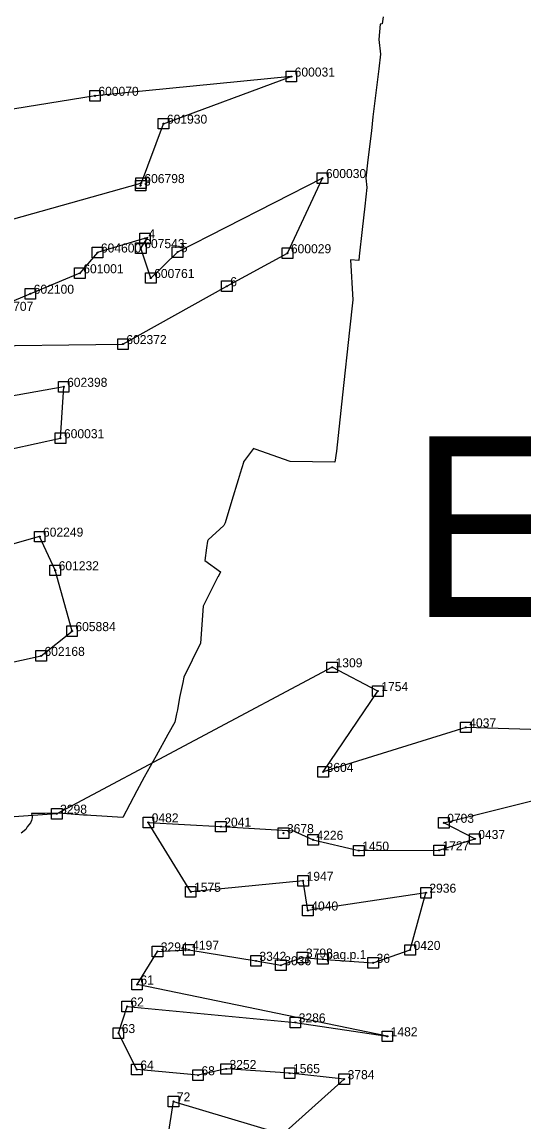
# Model space of a CAD drawing. Extents: x 462479 to 502016, y 241775 to 305873.
# Drawn here: x 478531 to 481857, y 250516 to 257820 of the extents above; entities that cross this region are included whole.
import ezdxf

# ---------------------------------------------------------------- set-up
doc = ezdxf.new("R2010")
doc.units = 0
for name, color, linetype in [('Default', 7, 'Continuous'), ('Level 19', 7, 'Continuous'), ('Level 51', 7, 'Continuous'), ('pagastu_nosaukumi', 7, 'Continuous'), ('pagastu_robezas', 7, 'Continuous')]:
    doc.layers.add(name, color=color, linetype=linetype)

msp = doc.modelspace()

# ---------------------------------------------------------------- linework, layer by layer
at = {"layer": 'Default'}
for points in [[(477812.9, 256327.6), (479320.6, 256750.3), (479318.1, 256733.4), (479470.4, 257144.7), (480318.7, 257457.6), (479015.3, 257329.8), (477784.6, 257129.8)], [(478123.9, 255667.8), (479201, 255681.3), (479891, 256065.7), (480293.6, 256284.5), (480525.8, 256783.7), (479562.7, 256291.9), (479385.7, 256120.1), (479319.9, 256318.4), (479366.3, 256388.8), (479032.1, 256289.4), (478915.1, 256151.7), (478585.9, 256015.6), (478315.6, 255902.1)], [(477814.9, 254844.2), (478786.8, 255056.3), (478807.5, 255397.6), (477838.5, 255223.9)], [(478003.4, 253467.4), (478657.4, 253610.8), (478862.7, 253775.4), (478751.3, 254179.4), (478647.6, 254402.7), (477546.7, 254091.6)], [(483413.2, 253074.8), (481478.2, 253136.4), (480530.5, 252840.5), (480894, 253377.2), (480590.4, 253535.2), (478761.2, 252562.9), (477780.4, 252492.7)], [(479499.4, 250412), (479536.6, 250652.6), (480263.2, 250435.7), (480670.4, 250800.4), (480308, 250840.1), (479886.1, 250868), (479699.6, 250826.5), (479293.6, 250864.3), (479170.4, 251106.6), (479228, 251283.1), (480345.5, 251177.2), (480956.2, 251085.1), (479294.5, 251428.9), (479429.7, 251648.6), (479637.8, 251659.4), (480084.6, 251586.1), (480249.8, 251556.8), (480393.6, 251607.8), (480579.8, 251593.8), (480862.8, 251573), (481108.4, 251658.5), (481213, 252038.4), (480429, 251920.3), (480397.8, 252117.5), (479650.8, 252044.3), (479369.2, 252505.4), (479851.3, 252477.2), (480333.5, 252449.1), (480463.4, 252389.8), (480767.1, 252317.8), (481299.9, 252320.1), (481537.6, 252395.2), (481331.4, 252502.6), (482023.1, 252674.5)]]:
    msp.add_lwpolyline(points, dxfattribs=at)
at = {"layer": 'Level 19'}
for p, q in [((480283.7, 257492.6), (480353.7, 257492.6)), ((480283.7, 257422.6), (480283.7, 257492.6)), ((480353.7, 257492.6), (480353.7, 257422.6)), ((480353.7, 257422.6), (480283.7, 257422.6)), ((478980.3, 257364.8), (479050.3, 257364.8)), ((478980.3, 257294.8), (478980.3, 257364.8)), ((479050.3, 257364.8), (479050.3, 257294.8)), ((479050.3, 257294.8), (478980.3, 257294.8)), ((479435.4, 257179.7), (479505.4, 257179.7)), ((479435.4, 257109.7), (479435.4, 257179.7)), ((479505.4, 257179.7), (479505.4, 257109.7)), ((479505.4, 257109.7), (479435.4, 257109.7)), ((480490.8, 256818.7), (480560.8, 256818.7)), ((480490.8, 256748.7), (480490.8, 256818.7)), ((480560.8, 256818.7), (480560.8, 256748.7)), ((479283.1, 256768.4), (479353.1, 256768.4)), ((479283.1, 256698.4), (479283.1, 256768.4)), ((479285.6, 256785.3), (479355.6, 256785.3)), ((479285.6, 256715.3), (479285.6, 256785.3)), ((479353.1, 256768.4), (479353.1, 256698.4)), ((479355.6, 256785.3), (479355.6, 256715.3)), ((480560.8, 256748.7), (480490.8, 256748.7)), ((479353.1, 256698.4), (479283.1, 256698.4)), ((479355.6, 256715.3), (479285.6, 256715.3)), ((479312.4, 256417.8), (479382.4, 256417.8)), ((479312.4, 256347.8), (479312.4, 256417.8)), ((479382.4, 256417.8), (479382.4, 256347.8)), ((478997.1, 256324.4), (479067.1, 256324.4)), ((478997.1, 256254.4), (478997.1, 256324.4)), ((479067.1, 256324.4), (479067.1, 256254.4)), ((479284.9, 256353.4), (479354.9, 256353.4)), ((479284.9, 256283.4), (479284.9, 256353.4)), ((479284.9, 256353.4), (479354.9, 256353.4)), ((479284.9, 256283.4), (479284.9, 256353.4)), ((479382.4, 256347.8), (479312.4, 256347.8)), ((479354.9, 256353.4), (479354.9, 256283.4)), ((479354.9, 256353.4), (479354.9, 256283.4)), ((479527.7, 256326.9), (479597.7, 256326.9)), ((479527.7, 256256.9), (479527.7, 256326.9)), ((479597.7, 256326.9), (479597.7, 256256.9)), ((480258.6, 256319.5), (480328.6, 256319.5)), ((480258.6, 256249.5), (480258.6, 256319.5)), ((480328.6, 256319.5), (480328.6, 256249.5)), ((479067.1, 256254.4), (478997.1, 256254.4)), ((479354.9, 256283.4), (479284.9, 256283.4)), ((479354.9, 256283.4), (479284.9, 256283.4)), ((479597.7, 256256.9), (479527.7, 256256.9)), ((480328.6, 256249.5), (480258.6, 256249.5)), ((478880.1, 256186.7), (478950.1, 256186.7)), ((478880.1, 256116.7), (478880.1, 256186.7)), ((478950.1, 256186.7), (478950.1, 256116.7)), ((479350.7, 256155.1), (479420.7, 256155.1)), ((479350.7, 256085.1), (479350.7, 256155.1)), ((479420.7, 256155.1), (479420.7, 256085.1)), ((478950.1, 256116.7), (478880.1, 256116.7)), ((479420.7, 256085.1), (479350.7, 256085.1)), ((479856, 256100.7), (479926, 256100.7)), ((479856, 256030.7), (479856, 256100.7)), ((479926, 256100.7), (479926, 256030.7)), ((478550.9, 256050.6), (478620.9, 256050.6)), ((478550.9, 255980.6), (478550.9, 256050.6)), ((478620.9, 256050.6), (478620.9, 255980.6)), ((479926, 256030.7), (479856, 256030.7)), ((478620.9, 255980.6), (478550.9, 255980.6)), ((479166, 255716.3), (479236, 255716.3)), ((479166, 255646.3), (479166, 255716.3)), ((479236, 255716.3), (479236, 255646.3)), ((479236, 255646.3), (479166, 255646.3)), ((478772.5, 255432.6), (478842.5, 255432.6)), ((478772.5, 255362.6), (478772.5, 255432.6)), ((478842.5, 255432.6), (478842.5, 255362.6)), ((478842.5, 255362.6), (478772.5, 255362.6)), ((478751.8, 255091.3), (478821.8, 255091.3)), ((478751.8, 255021.3), (478751.8, 255091.3)), ((478821.8, 255091.3), (478821.8, 255021.3)), ((478821.8, 255021.3), (478751.8, 255021.3)), ((478612.6, 254437.7), (478682.6, 254437.7)), ((478612.6, 254367.7), (478612.6, 254437.7)), ((478682.6, 254437.7), (478682.6, 254367.7)), ((478682.6, 254367.7), (478612.6, 254367.7)), ((478716.3, 254214.4), (478786.3, 254214.4)), ((478716.3, 254144.4), (478716.3, 254214.4)), ((478786.3, 254214.4), (478786.3, 254144.4)), ((478786.3, 254144.4), (478716.3, 254144.4)), ((478827.7, 253810.4), (478897.7, 253810.4)), ((478827.7, 253740.4), (478827.7, 253810.4)), ((478897.7, 253740.4), (478827.7, 253740.4)), ((478897.7, 253810.4), (478897.7, 253740.4)), ((478622.4, 253645.8), (478692.4, 253645.8)), ((478622.4, 253575.8), (478622.4, 253645.8)), ((478692.4, 253645.8), (478692.4, 253575.8)), ((478692.4, 253575.8), (478622.4, 253575.8)), ((480555.4, 253570.2), (480625.4, 253570.2)), ((480555.4, 253500.2), (480555.4, 253570.2)), ((480625.4, 253570.2), (480625.4, 253500.2)), ((480625.4, 253500.2), (480555.4, 253500.2)), ((480859, 253412.2), (480929, 253412.2)), ((480859, 253342.2), (480859, 253412.2)), ((480929, 253412.2), (480929, 253342.2)), ((480929, 253342.2), (480859, 253342.2)), ((481443.2, 253171.4), (481513.2, 253171.4)), ((481443.2, 253101.4), (481443.2, 253171.4)), ((481513.2, 253171.4), (481513.2, 253101.4)), ((481513.2, 253101.4), (481443.2, 253101.4)), ((480495.5, 252875.5), (480565.5, 252875.5)), ((480495.5, 252805.5), (480495.5, 252875.5)), ((480565.5, 252875.5), (480565.5, 252805.5)), ((480565.5, 252805.5), (480495.5, 252805.5)), ((478726.2, 252597.9), (478796.2, 252597.9)), ((478726.2, 252527.9), (478726.2, 252597.9)), ((478796.2, 252597.9), (478796.2, 252527.9)), ((478796.2, 252527.9), (478726.2, 252527.9)), ((479334.2, 252540.4), (479404.2, 252540.4)), ((479334.2, 252470.4), (479334.2, 252540.4)), ((479334.2, 252540.4), (479404.2, 252540.4)), ((479334.2, 252470.4), (479334.2, 252540.4)), ((479334.2, 252540.4), (479404.2, 252540.4)), ((479334.2, 252470.4), (479334.2, 252540.4)), ((479404.2, 252540.4), (479404.2, 252470.4)), ((479404.2, 252540.4), (479404.2, 252470.4)), ((479404.2, 252540.4), (479404.2, 252470.4)), ((479816.3, 252512.2), (479886.3, 252512.2)), ((479816.3, 252442.2), (479816.3, 252512.2)), ((479886.3, 252512.2), (479886.3, 252442.2)), ((481296.4, 252537.6), (481366.4, 252537.6)), ((481296.4, 252467.6), (481296.4, 252537.6)), ((481366.4, 252537.6), (481366.4, 252467.6)), ((479404.2, 252470.4), (479334.2, 252470.4)), ((479404.2, 252470.4), (479334.2, 252470.4)), ((479404.2, 252470.4), (479334.2, 252470.4)), ((479886.3, 252442.2), (479816.3, 252442.2)), ((480232.5, 252469), (480302.5, 252469)), ((480232.5, 252399), (480232.5, 252469)), ((480302.5, 252469), (480302.5, 252399)), ((480428.4, 252424.8), (480498.4, 252424.8)), ((480428.4, 252354.8), (480428.4, 252424.8)), ((480498.4, 252424.8), (480498.4, 252354.8)), ((481366.4, 252467.6), (481296.4, 252467.6)), ((481502.6, 252430.2), (481572.6, 252430.2)), ((481502.6, 252360.2), (481502.6, 252430.2)), ((481572.6, 252430.2), (481572.6, 252360.2)), ((480302.5, 252399), (480232.5, 252399)), ((480498.4, 252354.8), (480428.4, 252354.8)), ((480732.1, 252352.8), (480802.1, 252352.8)), ((480732.1, 252282.8), (480732.1, 252352.8)), ((480802.1, 252352.8), (480802.1, 252282.8)), ((481264.9, 252355.1), (481334.9, 252355.1)), ((481264.9, 252285.1), (481264.9, 252355.1)), ((481264.9, 252355.1), (481334.9, 252355.1)), ((481264.9, 252285.1), (481264.9, 252355.1)), ((481264.9, 252355.1), (481334.9, 252355.1)), ((481264.9, 252285.1), (481264.9, 252355.1)), ((481264.9, 252355.1), (481334.9, 252355.1)), ((481264.9, 252285.1), (481264.9, 252355.1)), ((481334.9, 252355.1), (481334.9, 252285.1)), ((481334.9, 252355.1), (481334.9, 252285.1)), ((481334.9, 252355.1), (481334.9, 252285.1)), ((481334.9, 252355.1), (481334.9, 252285.1)), ((481572.6, 252360.2), (481502.6, 252360.2)), ((480802.1, 252282.8), (480732.1, 252282.8)), ((481334.9, 252285.1), (481264.9, 252285.1)), ((481334.9, 252285.1), (481264.9, 252285.1)), ((481334.9, 252285.1), (481264.9, 252285.1)), ((481334.9, 252285.1), (481264.9, 252285.1)), ((480362.8, 252152.5), (480432.8, 252152.5)), ((480362.8, 252082.5), (480362.8, 252152.5)), ((480362.8, 252152.5), (480432.8, 252152.5)), ((480362.8, 252082.5), (480362.8, 252152.5)), ((480362.8, 252152.5), (480432.8, 252152.5)), ((480362.8, 252082.5), (480362.8, 252152.5)), ((480362.8, 252152.5), (480432.8, 252152.5)), ((480362.8, 252082.5), (480362.8, 252152.5)), ((480432.8, 252152.5), (480432.8, 252082.5)), ((480432.8, 252152.5), (480432.8, 252082.5)), ((480432.8, 252152.5), (480432.8, 252082.5)), ((480432.8, 252152.5), (480432.8, 252082.5)), ((479615.8, 252079.3), (479685.8, 252079.3)), ((479615.8, 252009.3), (479615.8, 252079.3)), ((479685.8, 252079.3), (479685.8, 252009.3)), ((480432.8, 252082.5), (480362.8, 252082.5)), ((480432.8, 252082.5), (480362.8, 252082.5)), ((480432.8, 252082.5), (480362.8, 252082.5)), ((480432.8, 252082.5), (480362.8, 252082.5)), ((481178, 252073.4), (481248, 252073.4)), ((481178, 252003.4), (481178, 252073.4)), ((481248, 252073.4), (481248, 252003.4)), ((479685.8, 252009.3), (479615.8, 252009.3)), ((481248, 252003.4), (481178, 252003.4)), ((480394, 251955.3), (480464, 251955.3)), ((480394, 251885.3), (480394, 251955.3)), ((480464, 251955.3), (480464, 251885.3)), ((480464, 251885.3), (480394, 251885.3)), ((479602.8, 251694.4), (479672.8, 251694.4)), ((479602.8, 251624.4), (479602.8, 251694.4)), ((479672.8, 251694.4), (479672.8, 251624.4)), ((479394.7, 251683.6), (479464.7, 251683.6)), ((479394.7, 251613.6), (479394.7, 251683.6)), ((479464.7, 251683.6), (479464.7, 251613.6)), ((479672.8, 251624.4), (479602.8, 251624.4)), ((480049.6, 251621.1), (480119.6, 251621.1)), ((480049.6, 251551.1), (480049.6, 251621.1)), ((480119.6, 251621.1), (480119.6, 251551.1)), ((480358.6, 251642.8), (480428.6, 251642.8)), ((480358.6, 251572.8), (480358.6, 251642.8)), ((480358.6, 251642.8), (480428.6, 251642.8)), ((480358.6, 251572.8), (480358.6, 251642.8)), ((480358.6, 251642.8), (480428.6, 251642.8)), ((480358.6, 251572.8), (480358.6, 251642.8)), ((480358.6, 251642.8), (480428.6, 251642.8)), ((480358.6, 251572.8), (480358.6, 251642.8)), ((480428.6, 251642.8), (480428.6, 251572.8)), ((480428.6, 251642.8), (480428.6, 251572.8)), ((480428.6, 251642.8), (480428.6, 251572.8)), ((480428.6, 251642.8), (480428.6, 251572.8)), ((480492.5, 251633.2), (480562.5, 251633.2)), ((480492.5, 251563.2), (480492.5, 251633.2)), ((480562.5, 251633.2), (480562.5, 251563.2)), ((481073.4, 251693.5), (481143.4, 251693.5)), ((481073.4, 251623.5), (481073.4, 251693.5)), ((481073.4, 251693.5), (481143.4, 251693.5)), ((481073.4, 251623.5), (481073.4, 251693.5)), ((481073.4, 251693.5), (481143.4, 251693.5)), ((481073.4, 251623.5), (481073.4, 251693.5)), ((481143.4, 251623.5), (481073.4, 251623.5)), ((481143.4, 251623.5), (481073.4, 251623.5)), ((481143.4, 251623.5), (481073.4, 251623.5)), ((481143.4, 251693.5), (481143.4, 251623.5)), ((481143.4, 251693.5), (481143.4, 251623.5)), ((481143.4, 251693.5), (481143.4, 251623.5)), ((479464.7, 251613.6), (479394.7, 251613.6)), ((480119.6, 251551.1), (480049.6, 251551.1)), ((480214.8, 251591.8), (480284.8, 251591.8)), ((480214.8, 251521.8), (480214.8, 251591.8)), ((480284.8, 251591.8), (480284.8, 251521.8)), ((480428.6, 251572.8), (480358.6, 251572.8)), ((480428.6, 251572.8), (480358.6, 251572.8)), ((480428.6, 251572.8), (480358.6, 251572.8)), ((480428.6, 251572.8), (480358.6, 251572.8)), ((480562.5, 251563.2), (480492.5, 251563.2)), ((480827.8, 251608), (480897.8, 251608)), ((480827.8, 251538), (480827.8, 251608)), ((480897.8, 251608), (480897.8, 251538)), ((480284.8, 251521.8), (480214.8, 251521.8)), ((480897.8, 251538), (480827.8, 251538)), ((479259.5, 251463.9), (479329.5, 251463.9)), ((479259.5, 251393.9), (479259.5, 251463.9)), ((479259.5, 251463.9), (479329.5, 251463.9)), ((479259.5, 251393.9), (479259.5, 251463.9)), ((479259.5, 251463.9), (479329.5, 251463.9)), ((479259.5, 251393.9), (479259.5, 251463.9)), ((479329.5, 251463.9), (479329.5, 251393.9)), ((479329.5, 251463.9), (479329.5, 251393.9)), ((479329.5, 251463.9), (479329.5, 251393.9)), ((479329.5, 251393.9), (479259.5, 251393.9)), ((479329.5, 251393.9), (479259.5, 251393.9)), ((479329.5, 251393.9), (479259.5, 251393.9)), ((479193, 251318.1), (479263, 251318.1)), ((479193, 251248.1), (479193, 251318.1)), ((479263, 251318.1), (479263, 251248.1)), ((479263, 251248.1), (479193, 251248.1)), ((480310.5, 251212.2), (480380.5, 251212.2)), ((480310.5, 251142.2), (480310.5, 251212.2)), ((480380.5, 251212.2), (480380.5, 251142.2)), ((479135.4, 251141.6), (479205.4, 251141.6)), ((479135.4, 251071.6), (479135.4, 251141.6)), ((479205.4, 251141.6), (479205.4, 251071.6)), ((480380.5, 251142.2), (480310.5, 251142.2)), ((480921.2, 251120.1), (480991.2, 251120.1)), ((480921.2, 251050.1), (480921.2, 251120.1)), ((480991.2, 251120.1), (480991.2, 251050.1)), ((479205.4, 251071.6), (479135.4, 251071.6)), ((480991.2, 251050.1), (480921.2, 251050.1)), ((479258.6, 250899.3), (479328.6, 250899.3)), ((479258.6, 250829.3), (479258.6, 250899.3)), ((479328.6, 250899.3), (479328.6, 250829.3)), ((479851.1, 250903), (479921.1, 250903)), ((479851.1, 250833), (479851.1, 250903)), ((479921.1, 250903), (479921.1, 250833)), ((479328.6, 250829.3), (479258.6, 250829.3)), ((479664.6, 250861.5), (479734.6, 250861.5)), ((479664.6, 250791.5), (479664.6, 250861.5)), ((479734.6, 250861.5), (479734.6, 250791.5)), ((479921.1, 250833), (479851.1, 250833)), ((480273, 250875.1), (480343, 250875.1)), ((480273, 250805.1), (480273, 250875.1)), ((480273, 250875.1), (480343, 250875.1)), ((480273, 250805.1), (480273, 250875.1)), ((480273, 250875.1), (480343, 250875.1)), ((480273, 250805.1), (480273, 250875.1)), ((480273, 250875.1), (480343, 250875.1)), ((480273, 250805.1), (480273, 250875.1)), ((480343, 250875.1), (480343, 250805.1)), ((480343, 250875.1), (480343, 250805.1)), ((480343, 250875.1), (480343, 250805.1)), ((480343, 250875.1), (480343, 250805.1)), ((480635.4, 250835.4), (480705.4, 250835.4)), ((480635.4, 250765.4), (480635.4, 250835.4)), ((480705.4, 250835.4), (480705.4, 250765.4)), ((479734.6, 250791.5), (479664.6, 250791.5)), ((480343, 250805.1), (480273, 250805.1)), ((480343, 250805.1), (480273, 250805.1)), ((480343, 250805.1), (480273, 250805.1)), ((480343, 250805.1), (480273, 250805.1)), ((480705.4, 250765.4), (480635.4, 250765.4)), ((479501.6, 250687.6), (479571.6, 250687.6)), ((479501.6, 250617.6), (479501.6, 250687.6)), ((479501.6, 250687.6), (479571.6, 250687.6)), ((479501.6, 250617.6), (479501.6, 250687.6)), ((479501.6, 250687.6), (479571.6, 250687.6)), ((479501.6, 250617.6), (479501.6, 250687.6)), ((479571.6, 250687.6), (479571.6, 250617.6)), ((479571.6, 250687.6), (479571.6, 250617.6)), ((479571.6, 250687.6), (479571.6, 250617.6)), ((479571.6, 250617.6), (479501.6, 250617.6)), ((479571.6, 250617.6), (479501.6, 250617.6)), ((479571.6, 250617.6), (479501.6, 250617.6))]:
    msp.add_line(p, q, dxfattribs=at)
for centre in [(480318.7, 257457.6), (479015.3, 257329.8), (479470.4, 257144.7), (479318.2, 256733.4), (479320.6, 256750.2), (480525.8, 256783.7), (479347.4, 256382.8), (479319.9, 256318.4), (479319.9, 256318.4), (479032.1, 256289.3), (479562.8, 256291.9), (480293.6, 256284.5), (478915.1, 256151.7), (479385.7, 256120.1), (478585.9, 256015.6), (479891, 256065.6), (479201, 255681.3), (478807.5, 255397.5), (478786.9, 255056.3), (478647.6, 254402.7), (478751.4, 254179.3), (478862.7, 253775.4), (478657.5, 253610.7), (480590.4, 253535.2), (480894, 253377.2), (481478.2, 253136.4), (480530.5, 252840.5), (478761.2, 252562.9), (479369.2, 252505.3), (479369.2, 252505.3), (479369.2, 252505.3), (481331.4, 252502.6), (479851.4, 252477.2), (480267.6, 252433.9), (480463.4, 252389.8), (481537.6, 252395.2), (480767.2, 252317.8), (481299.9, 252320.1), (481299.9, 252320.1), (481299.9, 252320.1), (481299.9, 252320.1), (480397.8, 252117.5), (480397.8, 252117.5), (480397.8, 252117.5), (480397.8, 252117.5), (479650.9, 252044.3), (481213, 252038.4), (480429.1, 251920.3), (479429.8, 251648.6), (479637.8, 251659.3), (481108.5, 251658.5), (481108.5, 251658.5), (481108.5, 251658.5), (480084.7, 251586), (480249.8, 251556.7), (480393.6, 251607.7), (480393.6, 251607.7), (480393.6, 251607.7), (480393.6, 251607.7), (480527.5, 251598.1), (480862.9, 251573), (479294.5, 251428.9), (479294.5, 251428.9), (479294.5, 251428.9), (479228.1, 251283.1), (479170.5, 251106.6), (480345.5, 251177.1), (480956.2, 251085), (479293.6, 250864.2), (479699.7, 250826.5), (479886.1, 250868), (480308, 250840.1), (480308, 250840.1), (480308, 250840.1), (480308, 250840.1), (480670.4, 250800.4), (479536.7, 250652.6), (479536.7, 250652.6), (479536.7, 250652.6)]:
    msp.add_circle(centre, 3.5, dxfattribs=at)
at = {"layer": 'pagastu_robezas'}
msp.add_lwpolyline([(480928.5, 257855.4), (480921.1, 257807.7), (480909.4, 257806.7), (480901, 257704), (480911.4, 257606.4), (480900.7, 257509.4), (480860.7, 257189.9), (480850.2, 257096.5), (480827.7, 256904.3), (480813.4, 256782.3), (480820.3, 256722.2), (480806, 256597), (480789.4, 256441.8), (480769.9, 256264.5), (480767.5, 256236.7), (480712.9, 256240.7), (480726.7, 255975.4), (480704.2, 255773), (480658.4, 255345.3), (480618.1, 254971.3), (480607.6, 254898.1), (480310.5, 254902.7), (480079.5, 254983.3), (480067.1, 254988.5), (480002, 254898.7), (480000.6, 254895.1), (479979, 254823.4), (479965.7, 254779.2), (479924.4, 254642.3), (479879.4, 254494.2), (479871.3, 254476.5), (479765.9, 254381.7), (479762.1, 254371.7), (479756.2, 254329.2), (479745.3, 254244.7), (479848.8, 254168.9), (479832.4, 254136.7), (479831.6, 254135.2), (479733, 253941.8), (479715.9, 253696), (479605, 253469.3), (479597.5, 253435), (479585, 253373.9), (479577.2, 253333.9), (479563.4, 253253.4), (479557.4, 253226.9), (479544.7, 253171.6), (479499.5, 253090.1), (479421, 252948.3), (479342.3, 252806.2), (479293.9, 252715.1), (479200.1, 252538.3), (479024.4, 252548.9), (478986.9, 252551.2), (478963.2, 252552.6), (478939.1, 252554.3), (478828.4, 252562.2), (478780.5, 252565.6), (478682.6, 252564.1), (478594.3, 252564.3), (478598.9, 252541.5), (478597.3, 252536.3), (478593.9, 252518.9), (478587.5, 252501.5), (478576.5, 252490.3), (478564.8, 252476.4), (478555.6, 252459), (478524, 252433.2)], dxfattribs=at)

# ---------------------------------------------------------------- texts
at = {"layer": 'Level 51'}
for s, p in [(' 600031', (480318.7, 257457.6)), (' 600070', (479015.3, 257329.8)), (' 601930', (479470.4, 257144.7)), (' 606798', (479320.6, 256750.3)), (' 600030', (480525.8, 256783.7)), (' 3', (479318.1, 256733.4)), (' 4', (479347.4, 256382.8)), (' 607543', (479319.9, 256318.4)), (' 607543', (479319.9, 256318.4)), (' 604600', (479032.1, 256289.4)), (' 5', (479562.7, 256291.9)), (' 600029', (480293.6, 256284.5)), (' 601001', (478915.1, 256151.7)), (' 600761', (479385.7, 256120.1)), (' 602100', (478585.9, 256015.6)), (' 6', (479891, 256065.7)), (' 606707', (478315.6, 255902.1)), (' 602372', (479201, 255681.3)), (' 602398', (478807.5, 255397.6)), (' 600031', (478786.8, 255056.3)), (' 602249', (478647.6, 254402.7)), (' 601232', (478751.3, 254179.4)), (' 605884', (478862.7, 253775.4)), (' 602168', (478657.4, 253610.8)), (' 1309', (480590.4, 253535.2)), (' 1754', (480894, 253377.2)), (' 4037', (481478.2, 253136.4)), (' 3604', (480530.5, 252840.5)), (' 3298', (478761.2, 252562.9)), (' 0482', (479369.2, 252505.4)), (' 0482', (479369.2, 252505.4)), (' 0482', (479369.2, 252505.4)), (' 2041', (479851.3, 252477.2)), (' 0703', (481331.4, 252502.6)), (' 3678', (480267.5, 252434)), (' 4226', (480463.4, 252389.8)), (' 0437', (481537.6, 252395.2)), (' 1450', (480767.1, 252317.8)), (' 1727', (481299.9, 252320.1)), (' 1727', (481299.9, 252320.1)), (' 1727', (481299.9, 252320.1)), (' 1727', (481299.9, 252320.1)), (' 1947', (480397.8, 252117.5)), (' 1947', (480397.8, 252117.5)), (' 1947', (480397.8, 252117.5)), (' 1947', (480397.8, 252117.5)), (' 1575', (479650.8, 252044.3)), (' 2936', (481213, 252038.4)), (' 4040', (480429, 251920.3)), (' 3294', (479429.7, 251648.6)), (' 4197', (479637.8, 251659.4)), (' 0420', (481108.4, 251658.5)), (' 0420', (481108.4, 251658.5)), (' 0420', (481108.4, 251658.5)), (' 3342', (480084.6, 251586.1)), (' 3798', (480393.6, 251607.8)), (' 3798', (480393.6, 251607.8)), (' 3798', (480393.6, 251607.8)), (' 3798', (480393.6, 251607.8)), (' pag.p.1', (480527.5, 251598.2)), (' 36', (480862.8, 251573)), (' 3036', (480249.8, 251556.8)), (' 61', (479294.5, 251428.9)), (' 61', (479294.5, 251428.9)), (' 61', (479294.5, 251428.9)), (' 62', (479228, 251283.1)), (' 3286', (480345.5, 251177.2)), (' 63', (479170.4, 251106.6)), (' 1482', (480956.2, 251085.1)), (' 64', (479293.6, 250864.3)), (' 3252', (479886.1, 250868)), (' 1565', (480308, 250840.1)), (' 1565', (480308, 250840.1)), (' 1565', (480308, 250840.1)), (' 1565', (480308, 250840.1)), (' 68', (479699.6, 250826.5)), (' 3784', (480670.4, 250800.4)), (' 72', (479536.6, 250652.6)), (' 72', (479536.6, 250652.6)), (' 72', (479536.6, 250652.6))]:
    msp.add_text(s, height=60, dxfattribs=at).set_placement(p)
at = {"layer": 'pagastu_nosaukumi'}
msp.add_text('Elejas', height=1200, dxfattribs=at).set_placement((481103.1, 253869.8))

doc.saveas('drawing.dxf')
